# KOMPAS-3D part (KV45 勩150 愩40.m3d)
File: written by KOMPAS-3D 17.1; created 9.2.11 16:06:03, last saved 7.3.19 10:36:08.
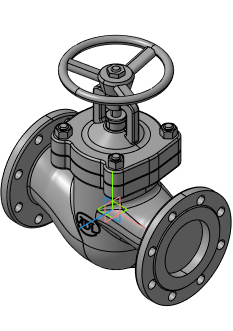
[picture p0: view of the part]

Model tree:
1. Плоскость XY
2. Плоскость ZX
3. Плоскость ZY
4. Ось X
5. Ось Y
6. Ось Z
7. Начало координат
8. Операция без истории:2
